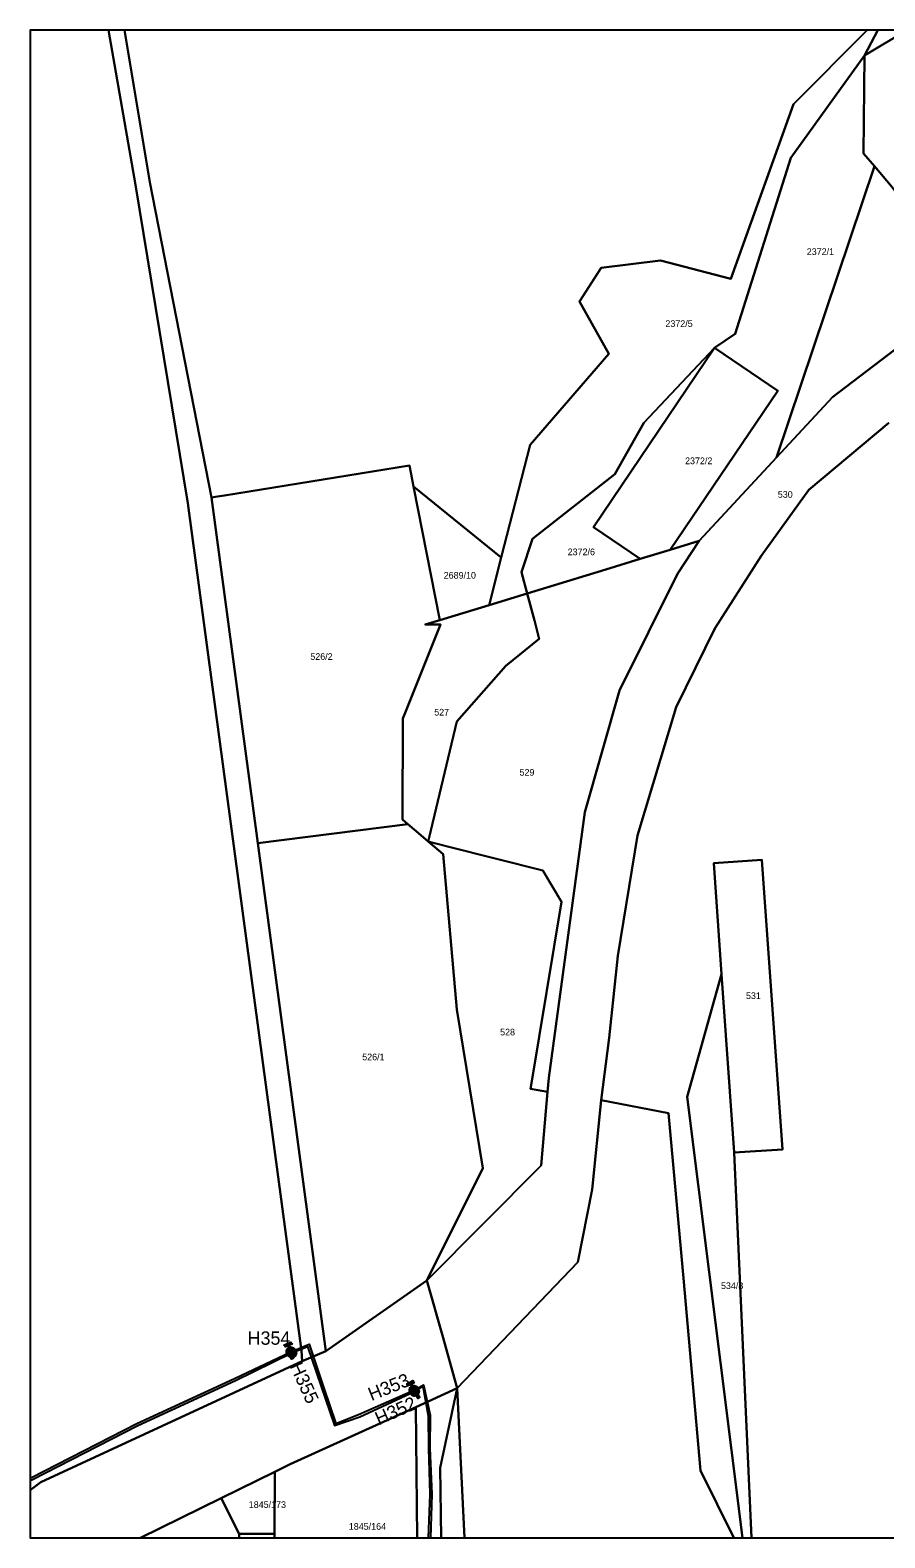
# Model space of a CAD drawing. Extents: x -561316 to -560969, y -1077679 to -1077341.
# Drawn here: x -561316.4 to -561124.4, y -1077679.3 to -1077340.8 of the extents above; entities that cross this region are included whole.
import ezdxf

# ---------------------------------------------------------------- set-up
doc = ezdxf.new("R2010")
doc.units = 0
for name, color, linetype in [('Hydrant', 7, 'Continuous'), ('Orientační sloupek', 7, 'Continuous'), ('Označení hydrantu', 7, 'Continuous'), ('Parcela-polygon', 7, 'Continuous'), ('Parcela-text', 7, 'Continuous'), ('Vodovodní řad', 7, 'Continuous')]:
    doc.layers.add(name, color=color, linetype=linetype)

msp = doc.modelspace()

# ---------------------------------------------------------------- linework, layer by layer
at = {"layer": 'Hydrant'}
for points in [[(-561258.28, -1077636.64), (-561258.6, -1077635.89), (-561259.24, -1077636.16), (-561259.31, -1077635.98), (-561257.87, -1077635.37), (-561257.8, -1077635.55), (-561258.43, -1077635.81), (-561258.11, -1077636.57)], [(-561258.08, -1077636.91), (-561258.39, -1077636.15), (-561259.02, -1077636.41), (-561259.09, -1077636.24), (-561257.65, -1077635.65), (-561257.57, -1077635.83), (-561258.21, -1077636.08), (-561257.91, -1077636.84)], [(-561258.2, -1077638.23), (-561257.59, -1077636.73)], [(-561257.42, -1077636.8), (-561258.03, -1077638.3)], [(-561258.02, -1077638.51), (-561257.39, -1077637.02)], [(-561257.22, -1077637.09), (-561257.85, -1077638.58)], [(-561230.72, -1077645.31), (-561231.11, -1077644.59), (-561231.71, -1077644.92), (-561231.8, -1077644.76), (-561230.43, -1077644.01), (-561230.34, -1077644.18), (-561230.94, -1077644.5), (-561230.55, -1077645.22)], [(-561230.56, -1077645.61), (-561230.9, -1077644.87), (-561231.53, -1077645.16), (-561231.61, -1077644.99), (-561230.19, -1077644.34), (-561230.11, -1077644.51), (-561230.73, -1077644.79), (-561230.39, -1077645.54)], [(-561230.48, -1077646.89), (-561230.02, -1077645.34)], [(-561230.43, -1077647.21), (-561229.87, -1077645.69)], [(-561229.84, -1077645.39), (-561230.3, -1077646.94)], [(-561229.69, -1077645.75), (-561230.25, -1077647.27)]]:
    msp.add_lwpolyline(points, dxfattribs=at)
for points in [[(-561258.11, -1077636.57), (-561257.77, -1077636.45), (-561257.43, -1077636.59), (-561257.05, -1077636.75), (-561256.89, -1077637.13), (-561256.73, -1077637.51), (-561256.88, -1077637.9), (-561257.04, -1077638.28), (-561257.42, -1077638.44), (-561257.8, -1077638.6), (-561258.18, -1077638.45), (-561258.57, -1077638.29), (-561258.73, -1077637.91), (-561258.89, -1077637.53), (-561258.74, -1077637.15), (-561258.6, -1077636.8), (-561258.28, -1077636.64)], [(-561257.59, -1077636.73), (-561257.86, -1077636.66), (-561258.13, -1077636.77), (-561258.44, -1077636.9), (-561258.57, -1077637.21), (-561258.69, -1077637.52), (-561258.56, -1077637.84), (-561258.45, -1077638.1), (-561258.2, -1077638.23)], [(-561257.91, -1077636.84), (-561257.56, -1077636.73), (-561257.23, -1077636.88), (-561256.85, -1077637.04), (-561256.69, -1077637.43), (-561256.54, -1077637.81), (-561256.7, -1077638.19), (-561256.86, -1077638.57), (-561257.25, -1077638.73), (-561257.63, -1077638.88), (-561258.01, -1077638.72), (-561258.39, -1077638.56), (-561258.55, -1077638.18), (-561258.7, -1077637.79), (-561258.54, -1077637.41), (-561258.4, -1077637.07), (-561258.08, -1077636.91)], [(-561257.39, -1077637.02), (-561257.66, -1077636.94), (-561257.93, -1077637.05), (-561258.24, -1077637.17), (-561258.37, -1077637.48), (-561258.5, -1077637.79), (-561258.38, -1077638.1), (-561258.27, -1077638.37), (-561258.02, -1077638.51)], [(-561258.03, -1077638.3), (-561257.76, -1077638.38), (-561257.49, -1077638.27), (-561257.19, -1077638.14), (-561257.06, -1077637.82), (-561256.93, -1077637.51), (-561257.06, -1077637.2), (-561257.18, -1077636.94), (-561257.42, -1077636.8)], [(-561257.85, -1077638.58), (-561257.59, -1077638.66), (-561257.32, -1077638.55), (-561257.01, -1077638.43), (-561256.88, -1077638.12), (-561256.74, -1077637.81), (-561256.87, -1077637.49), (-561256.98, -1077637.23), (-561257.22, -1077637.09)], [(-561230.55, -1077645.22), (-561230.23, -1077645.08), (-561229.88, -1077645.18), (-561229.48, -1077645.3), (-561229.28, -1077645.67), (-561229.08, -1077646.03), (-561229.2, -1077646.43), (-561229.32, -1077646.82), (-561229.68, -1077647.02), (-561230.05, -1077647.22), (-561230.44, -1077647.1), (-561230.84, -1077646.98), (-561231.04, -1077646.62), (-561231.24, -1077646.26), (-561231.12, -1077645.86), (-561231.02, -1077645.51), (-561230.72, -1077645.31)], [(-561230.39, -1077645.54), (-561230.06, -1077645.41), (-561229.71, -1077645.54), (-561229.33, -1077645.68), (-561229.15, -1077646.06), (-561228.98, -1077646.44), (-561229.12, -1077646.83), (-561229.26, -1077647.21), (-561229.64, -1077647.39), (-561230.02, -1077647.56), (-561230.41, -1077647.42), (-561230.79, -1077647.28), (-561230.97, -1077646.9), (-561231.14, -1077646.52), (-561231, -1077646.13), (-561230.88, -1077645.79), (-561230.56, -1077645.61)], [(-561230.02, -1077645.34), (-561230.3, -1077645.29), (-561230.55, -1077645.43), (-561230.85, -1077645.59), (-561230.94, -1077645.91), (-561231.04, -1077646.23), (-561230.88, -1077646.53), (-561230.74, -1077646.78), (-561230.48, -1077646.89)], [(-561229.87, -1077645.69), (-561230.14, -1077645.62), (-561230.4, -1077645.74), (-561230.71, -1077645.88), (-561230.83, -1077646.2), (-561230.94, -1077646.51), (-561230.8, -1077646.82), (-561230.68, -1077647.08), (-561230.43, -1077647.21)], [(-561230.3, -1077646.94), (-561230.03, -1077646.99), (-561229.77, -1077646.85), (-561229.48, -1077646.69), (-561229.38, -1077646.37), (-561229.29, -1077646.05), (-561229.45, -1077645.75), (-561229.59, -1077645.5), (-561229.84, -1077645.39)], [(-561230.25, -1077647.27), (-561229.98, -1077647.34), (-561229.72, -1077647.22), (-561229.42, -1077647.08), (-561229.3, -1077646.76), (-561229.18, -1077646.44), (-561229.32, -1077646.14), (-561229.45, -1077645.88), (-561229.69, -1077645.75)]]:
    msp.add_open_spline(points, degree=3, dxfattribs=at)
at = {"layer": 'Orientační sloupek'}
for points in [[(-561257.65, -1077638.62), (-561257.45, -1077638.52), (-561257.23, -1077638.97), (-561257.68, -1077639.19), (-561257.9, -1077638.74), (-561257.71, -1077638.64), (-561257.93, -1077638.19), (-561257.87, -1077638.17), (-561257.65, -1077638.62)], [(-561257.31, -1077638.94), (-561257.48, -1077638.6), (-561257.65, -1077638.68), (-561257.49, -1077639.02), (-561257.31, -1077638.94)], [(-561229.33, -1077647.44), (-561229.14, -1077647.32), (-561228.88, -1077647.75), (-561229.3, -1077648.01), (-561229.57, -1077647.59), (-561229.38, -1077647.47), (-561229.65, -1077647.05), (-561229.59, -1077647.01), (-561229.33, -1077647.44)], [(-561228.96, -1077647.72), (-561229.16, -1077647.4), (-561229.32, -1077647.5), (-561229.12, -1077647.83), (-561228.96, -1077647.72)]]:
    msp.add_lwpolyline(points, dxfattribs=at)
at = {"layer": 'Parcela-polygon'}
for p, q in [((-561295.19, -1077340.8), (-561298.8, -1077340.8)), ((-561128.32, -1077340.8), (-561295.19, -1077340.8)), ((-561125.97, -1077340.8), (-561128.32, -1077340.8)), ((-561119.43, -1077340.8), (-561125.97, -1077340.8)), ((-561291.62, -1077679.32), (-561269.48, -1077679.32)), ((-561269.48, -1077679.32), (-561261.48, -1077679.32)), ((-561261.48, -1077679.32), (-561229.46, -1077679.32)), ((-561229.46, -1077679.32), (-561224.08, -1077679.32)), ((-561224.08, -1077679.32), (-561218.79, -1077679.32)), ((-561218.79, -1077679.32), (-561158.31, -1077679.32)), ((-561158.31, -1077679.32), (-561156.34, -1077679.32)), ((-561156.34, -1077679.32), (-561154.34, -1077679.32)), ((-561154.34, -1077679.32), (-561091.55, -1077679.32))]:
    msp.add_line(p, q, dxfattribs=at)
for points in [[(-561298.8, -1077340.8), (-561316.42, -1077340.8), (-561316.42, -1077668.63)], [(-561316.42, -1077668.63), (-561314.04, -1077666.85), (-561255.27, -1077639.68), (-561255.45, -1077637.36), (-561280.98, -1077447), (-561292.75, -1077375.56), (-561298.8, -1077340.8)], [(-561298.8, -1077340.8), (-561292.75, -1077375.56), (-561280.98, -1077447), (-561255.45, -1077637.36), (-561255.27, -1077639.68), (-561250.01, -1077637.39), (-561265.29, -1077523.34), (-561275.69, -1077445.72), (-561289.5, -1077374.9), (-561295.19, -1077340.8)], [(-561295.19, -1077340.8), (-561289.5, -1077374.9), (-561275.69, -1077445.72), (-561274.29, -1077445.53), (-561272.76, -1077445.28), (-561231.2, -1077438.52), (-561230.27, -1077443.23), (-561210.56, -1077459.19), (-561204.09, -1077433.9), (-561186.4, -1077413.49), (-561192.98, -1077401.72), (-561188.12, -1077394.15), (-561174.75, -1077392.55), (-561158.98, -1077396.66), (-561144.88, -1077357.39), (-561128.32, -1077340.8)], [(-561128.32, -1077340.8), (-561144.88, -1077357.39), (-561158.98, -1077396.66), (-561174.75, -1077392.55), (-561188.12, -1077394.15), (-561192.98, -1077401.72), (-561186.4, -1077413.49), (-561204.09, -1077433.9), (-561210.56, -1077459.19), (-561213.3, -1077469.89), (-561204.72, -1077467.3), (-561206, -1077462.5), (-561203.5, -1077454.99), (-561185, -1077440.5), (-561178.5, -1077429), (-561162.63, -1077412.14), (-561158, -1077409), (-561145.5, -1077369.5), (-561128.95, -1077346.48), (-561125.97, -1077340.8)], [(-561119.43, -1077340.8), (-561128.95, -1077346.48), (-561129.16, -1077368.47), (-561126.69, -1077371.36), (-561122.71, -1077376.02), (-561117.62, -1077382.95), (-561109.74, -1077393.26), (-561104.98, -1077399.49), (-561089.39, -1077387.63), (-561091.5, -1077379.14), (-561098.94, -1077369.12), (-561099.03, -1077369.17), (-561101.03, -1077366.35), (-561105.36, -1077358.71), (-561112.78, -1077345.3), (-561114.76, -1077340.8)], [(-561125.97, -1077340.8), (-561128.95, -1077346.48), (-561119.43, -1077340.8)], [(-561104.98, -1077399.49), (-561136.14, -1077423.19), (-561148.69, -1077436.73), (-561166.06, -1077455.48), (-561170.96, -1077462.88), (-561183.96, -1077489.03), (-561191.75, -1077516.37), (-561199.85, -1077576.04), (-561200.13, -1077579.21), (-561201.58, -1077595.74), (-561227.29, -1077621.51), (-561223.64, -1077634.44), (-561221.13, -1077643.32), (-561220.44, -1077645.75), (-561193.37, -1077617.43), (-561190.16, -1077601.14), (-561188.09, -1077581.05), (-561186.29, -1077567.08), (-561184.34, -1077548.64), (-561179.96, -1077521.59), (-561171.23, -1077492.79), (-561162.55, -1077475.12), (-561152.1, -1077458.73), (-561141.46, -1077444.02), (-561123.47, -1077428.97)], [(-561123.47, -1077428.97), (-561141.46, -1077444.02), (-561152.1, -1077458.73), (-561162.55, -1077475.12), (-561171.23, -1077492.79), (-561179.96, -1077521.59), (-561184.34, -1077548.64), (-561186.29, -1077567.08), (-561188.09, -1077581.05), (-561173, -1077584), (-561169.61, -1077621), (-561165.8, -1077664.2), (-561158.31, -1077679.32)], [(-561156.34, -1077679.32), (-561168.8, -1077580.32), (-561161.05, -1077552.79), (-561162.82, -1077527.83), (-561152.01, -1077527.06), (-561147.33, -1077592.1), (-561158.21, -1077592.83), (-561154.34, -1077679.32)], [(-561154.34, -1077679.32), (-561158.21, -1077592.83), (-561161.05, -1077552.79), (-561168.8, -1077580.32), (-561156.34, -1077679.32)], [(-561158.31, -1077679.32), (-561165.8, -1077664.2), (-561169.61, -1077621), (-561173, -1077584), (-561188.09, -1077581.05), (-561190.16, -1077601.14), (-561193.37, -1077617.43), (-561220.44, -1077645.75), (-561218.79, -1077679.32)], [(-561291.62, -1077679.32), (-561273.46, -1077670.38), (-561261.47, -1077664.48), (-561257.96, -1077662.75), (-561229.77, -1077649.99), (-561220.44, -1077645.75), (-561221.13, -1077643.32), (-561223.64, -1077634.44), (-561227.29, -1077621.51), (-561250.01, -1077637.39), (-561255.27, -1077639.68), (-561314.04, -1077666.85), (-561316.42, -1077668.63)], [(-561224.08, -1077679.32), (-561224.28, -1077663.57), (-561220.44, -1077645.75), (-561229.77, -1077649.99), (-561229.46, -1077679.32)], [(-561218.79, -1077679.32), (-561220.44, -1077645.75), (-561224.28, -1077663.57), (-561224.08, -1077679.32)], [(-561229.46, -1077679.32), (-561229.77, -1077649.99), (-561257.96, -1077662.75), (-561261.47, -1077664.48), (-561261.48, -1077678.44), (-561261.48, -1077679.32)], [(-561316.42, -1077668.63), (-561316.42, -1077679.32), (-561291.62, -1077679.32)], [(-561269.48, -1077679.32), (-561269.48, -1077678.43), (-561273.46, -1077670.38), (-561291.62, -1077679.32)], [(-561261.48, -1077679.32), (-561261.48, -1077678.44), (-561269.48, -1077678.43), (-561269.48, -1077679.32)]]:
    msp.add_lwpolyline(points, dxfattribs=at)
for points in [[(-561158, -1077409), (-561162.63, -1077412.14), (-561148.39, -1077421.81), (-561172.61, -1077457.48), (-561166.06, -1077455.48), (-561148.69, -1077436.73), (-561126.69, -1077371.36), (-561129.16, -1077368.47), (-561128.95, -1077346.48), (-561145.5, -1077369.5)], [(-561148.69, -1077436.73), (-561136.14, -1077423.19), (-561104.98, -1077399.49), (-561109.74, -1077393.26), (-561117.62, -1077382.95), (-561122.71, -1077376.02), (-561126.69, -1077371.36)], [(-561203.5, -1077454.99), (-561206, -1077462.5), (-561204.72, -1077467.3), (-561187.05, -1077461.88), (-561179.36, -1077459.53), (-561189.86, -1077452.41), (-561162.63, -1077412.14), (-561178.5, -1077429), (-561185, -1077440.5)], [(-561162.63, -1077412.14), (-561189.86, -1077452.41), (-561179.36, -1077459.53), (-561172.61, -1077457.48), (-561148.39, -1077421.81)], [(-561272.76, -1077445.28), (-561274.29, -1077445.53), (-561275.69, -1077445.72), (-561265.29, -1077523.34), (-561231.51, -1077519.1), (-561232.74, -1077518.04), (-561232.68, -1077495.34), (-561232.18, -1077494.09), (-561224.18, -1077474.25), (-561227.65, -1077474.26), (-561224.37, -1077473.26), (-561230.27, -1077443.23), (-561231.2, -1077438.52)], [(-561230.27, -1077443.23), (-561224.37, -1077473.26), (-561213.3, -1077469.89), (-561210.56, -1077459.19)], [(-561204.72, -1077467.3), (-561203.11, -1077473.36), (-561202.01, -1077477.49), (-561209.5, -1077483.5), (-561220.5, -1077496), (-561226.77, -1077522.04), (-561227, -1077523), (-561222.35, -1077524.18), (-561201.2, -1077529.5), (-561197, -1077536.5), (-561203.71, -1077576.78), (-561204, -1077578.5), (-561200.13, -1077579.21), (-561199.85, -1077576.04), (-561191.75, -1077516.37), (-561183.96, -1077489.03), (-561170.96, -1077462.88), (-561166.06, -1077455.48), (-561172.61, -1077457.48), (-561179.36, -1077459.53), (-561187.05, -1077461.88)], [(-561232.18, -1077494.09), (-561232.68, -1077495.34), (-561232.74, -1077518.04), (-561231.51, -1077519.1), (-561229.71, -1077520.64), (-561227, -1077523), (-561226.77, -1077522.04), (-561220.5, -1077496), (-561209.5, -1077483.5), (-561202.01, -1077477.49), (-561203.11, -1077473.36), (-561204.72, -1077467.3), (-561213.3, -1077469.89), (-561224.37, -1077473.26), (-561227.65, -1077474.26), (-561224.18, -1077474.25)], [(-561231.51, -1077519.1), (-561265.29, -1077523.34), (-561250.01, -1077637.39), (-561227.29, -1077621.51), (-561214.72, -1077596.32), (-561220.54, -1077560.66), (-561223.63, -1077525.85), (-561227, -1077523), (-561229.71, -1077520.64)], [(-561214.72, -1077596.32), (-561227.29, -1077621.51), (-561201.58, -1077595.74), (-561200.13, -1077579.21), (-561204, -1077578.5), (-561203.71, -1077576.78), (-561197, -1077536.5), (-561201.2, -1077529.5), (-561222.35, -1077524.18), (-561227, -1077523), (-561223.63, -1077525.85), (-561220.54, -1077560.66)], [(-561152.01, -1077527.06), (-561162.82, -1077527.83), (-561161.05, -1077552.79), (-561158.21, -1077592.83), (-561147.33, -1077592.1)], [(-561261.47, -1077664.48), (-561273.46, -1077670.38), (-561269.48, -1077678.43), (-561261.48, -1077678.44)]]:
    msp.add_lwpolyline(points, close=True, dxfattribs=at)
at = {"layer": 'Vodovodní řad'}
for points in [[(-561316.42, -1077665.97), (-561316.23, -1077665.85), (-561292.42, -1077653.63), (-561270.53, -1077643.58), (-561257.81, -1077637.52)], [(-561316.42, -1077666.56), (-561316.01, -1077666.3), (-561292.22, -1077654.09), (-561270.3, -1077644.02), (-561257.62, -1077637.8)], [(-561257.81, -1077637.52), (-561253.75, -1077635.8), (-561252.09, -1077640.77), (-561250.43, -1077645.74), (-561247.69, -1077653.62), (-561242.61, -1077651.66), (-561230.22, -1077646.18), (-561230.16, -1077646.14)], [(-561257.62, -1077637.8), (-561254.08, -1077636.37), (-561247.99, -1077654.11), (-561242.32, -1077652.14), (-561230.06, -1077646.48)], [(-561230.16, -1077646.14), (-561228.01, -1077644.98), (-561226.53, -1077651.81), (-561226.58, -1077659.21), (-561226.17, -1077669.52), (-561226.46, -1077679.32)], [(-561230.06, -1077646.48), (-561228.16, -1077645.3), (-561226.94, -1077651.89), (-561226.93, -1077659.21), (-561226.64, -1077669.52), (-561226.97, -1077679.32)]]:
    msp.add_lwpolyline(points, dxfattribs=at)

# ---------------------------------------------------------------- texts
at = {"layer": 'Označení hydrantu'}
msp.add_text('H354', height=3, dxfattribs=at).set_placement((-561267.54, -1077635.97))
for s, rotation, p in [('H355', 294.444, (-561258.13, -1077640.75)), ('H353', 21.9606, (-561239.71, -1077648.63)), ('H352', 23.7174, (-561238.09, -1077654.09))]:
    msp.add_text(s, height=3, rotation=rotation, dxfattribs=at).set_placement(p)
at = {"layer": 'Parcela-text'}
for s, p in [('2372/1', (-561141.9, -1077391.28)), ('2372/5', (-561173.67, -1077407.44)), ('2372/2', (-561169.25, -1077438.25)), ('530', (-561148.41, -1077445.79)), ('2372/6', (-561195.63, -1077458.69)), ('2689/10', (-561223.49, -1077463.95)), ('526/2', (-561253.46, -1077482.19)), ('527', (-561225.62, -1077494.69)), ('529', (-561206.44, -1077508.19)), ('531', (-561155.56, -1077558.34)), ('528', (-561210.81, -1077566.51)), ('526/1', (-561241.8, -1077572.09)), ('534/8', (-561161.18, -1077623.46)), ('1845/173', (-561267.29, -1077672.6)), ('1845/164', (-561244.81, -1077677.51))]:
    msp.add_text(s, height=1.5, dxfattribs=at).set_placement(p)

doc.saveas('drawing.dxf')
